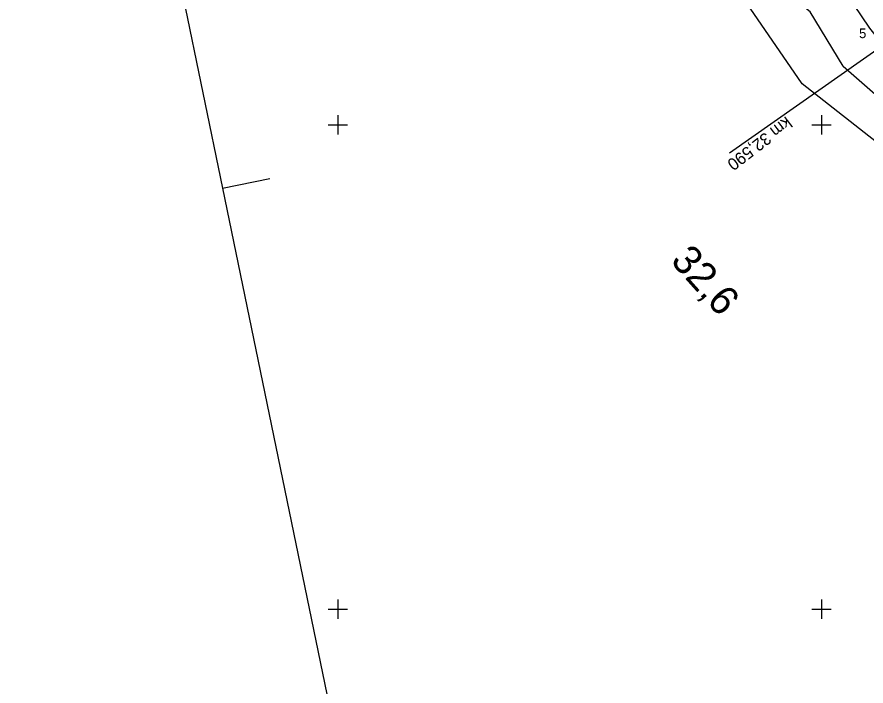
# Model space of a CAD drawing. Extents: x -804166 to -803706, y -1151030 to -1150147.
# Drawn here: x -804166.3 to -803990.8, y -1150515.9 to -1150377.7 of the extents above; entities that cross this region are included whole.
import ezdxf

# ---------------------------------------------------------------- set-up
doc = ezdxf.new("R2010")
doc.units = 0
for name, color, linetype in [('0381KM032-037P - Vrstva 3', 7, 'Continuous'), ('0381KM032-037P - Vrstva 49', 7, 'Continuous'), ('0381KM032-037P - Vrstva 7', 7, 'Continuous'), ('Default', 7, 'Continuous'), ('formát', 7, 'Continuous'), ('hran DP - hran DP', 7, 'Continuous'), ('krizky_1000 - Vrstva 1', 7, 'Continuous'), ('PSR_C2_2_trasa_Vimperk - Kabelová trasa', 7, 'Continuous')]:
    doc.layers.add(name, color=color, linetype=linetype)

msp = doc.modelspace()

# ---------------------------------------------------------------- linework, layer by layer
at = {"layer": '0381KM032-037P - Vrstva 3'}
msp.add_line((-803980.37, -1150378.68), (-804019.01, -1150405.81), dxfattribs=at)
at = {"layer": '0381KM032-037P - Vrstva 49'}
for points in [[(-803995.51, -1150387.87), (-804002.35, -1150376.64), (-804007.46, -1150372.51), (-804011.72, -1150371.94), (-804015.88, -1150373.24)], [(-803995.51, -1150387.87), (-803978.95, -1150402.37), (-803967.97, -1150412.01), (-803952.57, -1150434.32)]]:
    msp.add_lwpolyline(points, dxfattribs=at)
at = {"layer": 'formát'}
for p, q in [((-804166.3, -1150207.4), (-804123.84, -1150413.06)), ((-804123.84, -1150413.06), (-804114.04, -1150411.04)), ((-804123.84, -1150413.06), (-804081.38, -1150618.72))]:
    msp.add_line(p, q, dxfattribs=at)
at = {"layer": 'hran DP - hran DP'}
for p, q in [((-804004.05, -1150391.51), (-804033.86, -1150347.88)), ((-803965.92, -1150421.41), (-804004.05, -1150391.51))]:
    msp.add_line(p, q, dxfattribs=at)
at = {"layer": 'krizky_1000 - Vrstva 1'}
for points in [[(-804100, -1150398), (-804100, -1150402)], [(-804000, -1150398), (-804000, -1150402)], [(-804102, -1150400), (-804098, -1150400)], [(-804002, -1150400), (-803998, -1150400)], [(-804100, -1150498), (-804100, -1150502)], [(-804000, -1150498), (-804000, -1150502)], [(-804102, -1150500), (-804098, -1150500)], [(-804002, -1150500), (-803998, -1150500)]]:
    msp.add_lwpolyline(points, dxfattribs=at)
at = {"layer": 'PSR_C2_2_trasa_Vimperk - Kabelová trasa'}
msp.add_lwpolyline([(-804006.07, -1150356.3), (-803990.08, -1150380.01), (-803977.68, -1150395.4)], dxfattribs=at)

# ---------------------------------------------------------------- texts
at = {"layer": '0381KM032-037P - Vrstva 3'}
msp.add_text('km 32,590', height=2.5, rotation=217.4866, dxfattribs=at).set_placement((-804007.35, -1150398.11))
at = {"layer": '0381KM032-037P - Vrstva 7'}
msp.add_text('32,6', height=6, rotation=311.8828, dxfattribs=at).set_placement((-804031.4, -1150428.19))
at = {"layer": 'Default'}
msp.add_text('5', height=2, dxfattribs=at).set_placement((-803992.25, -1150382.07))

doc.saveas('drawing.dxf')
